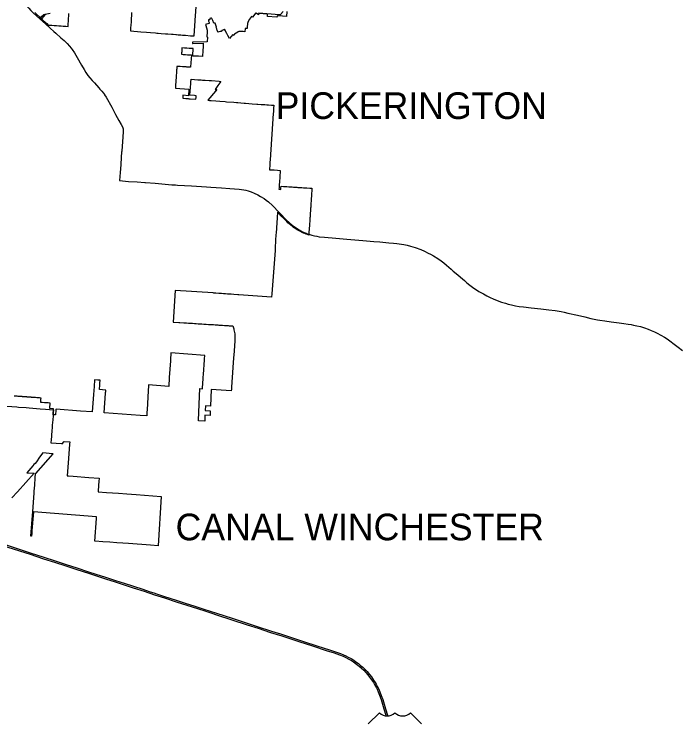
# Model space of a CAD drawing. Extents: x 1801177 to 2073177, y 551183 to 727183.
# Drawn here: x 1891384 to 1919316, y 663604 to 693418 of the extents above; entities that cross this region are included whole.
import ezdxf

# ---------------------------------------------------------------- set-up
doc = ezdxf.new("R2010")
doc.units = 0
for name, color, linetype in [('GM_X_Corporation', 7, 'Continuous'), ('GM_X_Corporation_Text', 7, 'Continuous'), ('GM_X_State_Route', 7, 'Continuous'), ('GM_X_US_Shield', 7, 'Continuous'), ('UT_P_Electric', 7, 'Continuous')]:
    doc.layers.add(name, color=color, linetype=linetype)

msp = doc.modelspace()

# ---------------------------------------------------------------- linework, layer by layer
at = {"layer": 'GM_X_Corporation'}
for points in [[(1901546, 693471), (1901398, 693294), (1901361, 693325), (1901361, 693325), (1901269, 693214), (1901224, 693105), (1901191, 693027), (1901179, 692875), (1901175, 692815), (1901136, 692818), (1901092, 692822), (1901081, 692677), (1901001, 692684), (1900921, 692690), (1900841, 692696), (1900824, 692697), (1900787, 692674), (1900780, 692669), (1900715, 692627), (1900643, 692582), (1900614, 692529), (1900600, 692538), (1900586, 692548), (1900574, 692558), (1900428, 692395), (1900362, 692521), (1900315, 692610), (1900269, 692699), (1900260, 692715), (1900220, 692793), (1900217, 692791), (1900202, 692781), (1900151, 692749), (1900115, 692726), (1900104, 692719), (1900096, 692714), (1900098, 692700), (1900098, 692686), (1900038, 692686), (1899944, 692665), (1899942, 692670), (1899918, 692741), (1899906, 692776), (1899896, 692805), (1899887, 692834), (1899877, 692862), (1899891, 692867), (1899827, 693044), (1899827, 693045), (1899778, 693044), (1899727, 693147), (1899670, 693262), (1899661, 693258), (1899644, 693250), (1899627, 693244), (1899622, 693241), (1899617, 693238), (1899612, 693234), (1899609, 693229), (1899606, 693224), (1899604, 693218), (1899604, 693212), (1899604, 693206), (1899606, 693190), (1899593, 693188), (1899576, 693186), (1899560, 693184), (1899546, 693183), (1899549, 693165), (1899550, 693154), (1899553, 693137), (1899557, 693120), (1899573, 693065), (1899584, 693030), (1899581, 693029), (1899566, 693024), (1899428, 692983), (1899440, 692942), (1899498, 692747), (1899495, 692702), (1899493, 692678), (1899475, 692460), (1899514, 692456), (1899497, 692257), (1898898, 692243), (1898880, 692243), (1898876, 692183), (1898894, 692183), (1899331, 692195), (1899321, 692045), (1899311, 691895), (1899293, 691645), (1899133, 691648), (1898886, 691654), (1898894, 691765), (1898903, 691890), (1898909, 691973), (1898879, 691975), (1898837, 691977), (1898737, 691983), (1898636, 691989), (1898536, 691995), (1898535, 691995), (1898435, 692001), (1898428, 691902), (1898426, 691866), (1898424, 691839), (1898421, 691790), (1898417, 691732), (1898492, 691728), (1898582, 691722), (1898672, 691717), (1898818, 691708), (1898830, 691707), (1898795, 691208), (1898793, 691189), (1898781, 691190), (1898634, 691198), (1898607, 691200), (1898544, 691204), (1898455, 691209), (1898365, 691214), (1898275, 691220), (1898223, 691223), (1898218, 691153), (1898215, 691119), (1898212, 691078), (1898207, 691003), (1898206, 690994), (1898193, 690803), (1898188, 690728), (1898183, 690662), (1898179, 690611), (1898176, 690569), (1898169, 690459), (1898163, 690384), (1898158, 690304), (1898729, 690271), (1898709, 689993), (1898475, 690012), (1898474, 690008), (1898466, 689889), (1898481, 689887), (1898593, 689878), (1898611, 689876), (1898694, 689869), (1898730, 689866), (1898735, 689866), (1898775, 689863), (1899020, 689844), (1899025, 689923), (1899030, 689993), (1898958, 689999), (1898770, 690013), (1898782, 690178), (1898794, 690343), (1898805, 690507), (1898806, 690516), (1898806, 690521), (1898809, 690564), (1898818, 690688), (1899106, 690666), (1899222, 690657), (1899249, 690655), (1899294, 690652), (1899318, 690651), (1899404, 690645), (1899417, 690644), (1899575, 690633), (1899634, 690629), (1899677, 690626), (1900000, 690602), (1900070, 690597), (1899946, 690421), (1899833, 690261), (1899904, 690256), (1899845, 690186), (1899525, 689803), (1899556, 689801), (1899562, 689800), (1899592, 689798), (1899597, 689798), (1899660, 689793), (1899863, 689776), (1900023, 689764), (1900249, 689746), (1900254, 689745), (1900304, 689741), (1900611, 689718), (1900729, 689709), (1900778, 689705), (1900906, 689695), (1901046, 689683), (1901065, 689682), (1901105, 689679), (1901379, 689657), (1901578, 689642), (1901608, 689640), (1901616, 689639), (1901622, 689639), (1901764, 689629), (1901816, 689625), (1901919, 689617), (1901922, 689617), (1901995, 689612), (1902071, 689606), (1902075, 689606), (1902199, 689597), (1902207, 689596), (1902293, 689590), (1902285, 689468), (1902275, 689310), (1902270, 689240), (1902139, 687299), (1902132, 687198), (1902122, 687046), (1902115, 686941), (1902112, 686886), (1902199, 686881), (1902309, 686873), (1902446, 686864), (1902564, 686856), (1902559, 686783), (1902550, 686636), (1902542, 686517), (1902536, 686434), (1902531, 686354), (1902525, 686258), (1902521, 686196), (1902515, 686117), (1902510, 686064), (1902592, 686059), (1902593, 686065), (1902593, 686071), (1902595, 686102), (1902601, 686190), (1902706, 686183), (1902772, 686179), (1902825, 686175), (1902849, 686174), (1902930, 686168), (1902962, 686166), (1902992, 686164), (1903071, 686159), (1903128, 686155), (1903191, 686151), (1903261, 686146), (1903311, 686143), (1903331, 686142), (1903401, 686137), (1903441, 686134), (1903470, 686132), (1903540, 686128), (1903561, 686126), (1903610, 686123), (1903680, 686118), (1903680, 686118), (1903806, 686110), (1903807, 686110), (1903898, 686104), (1903898, 686100), (1903893, 686026), (1903890, 685981), (1903885, 685904), (1903880, 685840), (1903879, 685826), (1903877, 685795), (1903875, 685756), (1903870, 685687), (1903868, 685654), (1903865, 685617), (1903863, 685581), (1903860, 685547), (1903857, 685497), (1903856, 685477), (1903851, 685407), (1903849, 685381), (1903846, 685337), (1903844, 685312), (1903841, 685267), (1903840, 685246), (1903839, 685235), (1903837, 685204), (1903824, 685011), (1903817, 684913), (1903817, 684908), (1903814, 684866), (1903814, 684863), (1903810, 684805), (1903808, 684786), (1903807, 684772), (1903793, 684556), (1903771, 684248), (1903768, 684197), (1903767, 684180), (1903764, 684141), (1903708, 684159), (1903652, 684180), (1903596, 684201), (1903541, 684225), (1903480, 684252), (1903420, 684282), (1903359, 684314), (1903299, 684348), (1903240, 684384), (1903183, 684422), (1903126, 684461), (1903065, 684507), (1903005, 684555), (1902947, 684604), (1902890, 684656), (1902836, 684710), (1902826, 684719), (1902798, 684748), (1902656, 684892), (1902637, 684911), (1902447, 685104), (1902445, 685080), (1902388, 684216), (1902385, 684163), (1902369, 683915), (1902365, 683849), (1902355, 683653), (1902352, 683582), (1902347, 683499), (1902346, 683483), (1902209, 681674), (1902199, 681533), (1900821, 681628), (1900776, 681631), (1900617, 681642), (1900502, 681650), (1900422, 681656), (1900342, 681662), (1900263, 681667), (1900183, 681673), (1900103, 681679), (1899990, 681687), (1899855, 681696), (1899779, 681702), (1899742, 681705), (1898151, 681815), (1898060, 680482), (1898307, 680467), (1898352, 680464), (1898508, 680454), (1898627, 680446), (1898710, 680441), (1898716, 680440), (1898776, 680436), (1898796, 680435), (1898876, 680430), (1898956, 680425), (1899036, 680420), (1899116, 680415), (1899195, 680409), (1899275, 680404), (1899355, 680399), (1899455, 680393), (1899545, 680387), (1899557, 680386), (1899635, 680381), (1899703, 680377), (1899729, 680375), (1899754, 680374), (1899824, 680369), (1899904, 680364), (1899949, 680361), (1899984, 680359), (1900064, 680354), (1900144, 680348), (1900223, 680343), (1900228, 680343), (1900303, 680338), (1900383, 680333), (1900412, 680331), (1900451, 680329), (1900558, 680322), (1900560, 680322), (1900569, 680321), (1900583, 680283), (1900596, 680244), (1900608, 680204), (1900621, 680152), (1900633, 680099), (1900643, 680046), (1900651, 679992), (1900656, 679939), (1900660, 679885), (1900661, 679831), (1900661, 679776), (1900658, 679722), (1900654, 679667), (1900643, 679512), (1900625, 679252), (1900606, 678987), (1900578, 678575), (1900520, 677744), (1900513, 677646), (1900509, 677594), (1900499, 677595), (1899662, 677654), (1899633, 676952), (1899418, 676967), (1899410, 676768), (1899625, 676752), (1899617, 676556), (1899402, 676571), (1899393, 676346), (1899392, 676321), (1899125, 676339), (1899127, 676365), (1899182, 677688), (1899297, 677680), (1899304, 677787), (1899305, 677804), (1899307, 677829), (1899309, 677854), (1899316, 677954), (1899319, 678001), (1899321, 678034), (1899325, 678091), (1899327, 678114), (1899332, 678193), (1899337, 678254), (1899338, 678273), (1899340, 678304), (1899344, 678353), (1899348, 678415), (1899353, 678483), (1899358, 678556), (1899362, 678612), (1899362, 678612), (1899368, 678700), (1899381, 678882), (1899382, 678907), (1899384, 678932), (1899394, 679078), (1897973, 679184), (1897954, 678897), (1897951, 678848), (1897904, 678150), (1897879, 677780), (1897028, 677848), (1897025, 677798), (1897013, 677593), (1896968, 676798), (1896962, 676701), (1896953, 676540), (1896673, 676561), (1896295, 676588), (1895170, 676671), (1895226, 677499), (1895228, 677529), (1895231, 677566), (1895235, 677622), (1895215, 677624), (1894966, 677643), (1894979, 677842), (1894984, 677917), (1894993, 678042), (1894899, 678049), (1894760, 678060), (1894760, 678059), (1894740, 677769), (1894718, 677442), (1894718, 677442), (1894706, 677260), (1894668, 676708), (1894164, 676746), (1893142, 676825), (1893141, 676808), (1893140, 676788), (1893123, 676580), (1893023, 676588), (1893028, 676658), (1893040, 676798), (1893040, 676806), (1893041, 676816), (1893042, 676833), (1892881, 676846), (1892883, 676868), (1892898, 677078), (1892811, 677085), (1892789, 677086), (1892750, 677089), (1892699, 677093), (1892664, 677096), (1892560, 677104), (1892499, 677109), (1892507, 677202), (1892508, 677218), (1892509, 677237), (1892513, 677288), (1892454, 677293), (1892404, 677297), (1892394, 677297), (1892334, 677302), (1892274, 677307), (1892249, 677309), (1892214, 677311), (1892155, 677316), (1892110, 677319), (1892095, 677321), (1892058, 677323), (1892035, 677325), (1891975, 677330), (1891915, 677334), (1891911, 677335), (1891855, 677339), (1891796, 677344), (1891736, 677348), (1891722, 677349), (1891711, 677350), (1891676, 677353), (1891616, 677358), (1891556, 677362), (1891512, 677366), (1891505, 677366), (1891497, 677367), (1891437, 677371), (1891377, 677376)], [(1892246, 693483), (1892526, 693225), (1892600, 693158), (1892679, 693087), (1892754, 693021), (1892817, 692963), (1892859, 692960), (1892868, 692960), (1892965, 692953), (1893063, 692946), (1893161, 692939), (1893259, 692932), (1893332, 692927), (1893356, 692925), (1893445, 692919), (1893454, 692918), (1893552, 692911), (1893646, 692904), (1893656, 693044), (1893660, 693104), (1893671, 693244), (1893678, 693343), (1893685, 693443)], [(1896321, 693489), (1896312, 693361), (1896310, 693337), (1896305, 693260), (1896300, 693188), (1896300, 693180), (1896294, 693090), (1896286, 692976), (1896276, 692837), (1896268, 692716), (1896708, 692680), (1896944, 692662), (1897112, 692648), (1897317, 692632), (1897373, 692627), (1897439, 692622), (1897564, 692612), (1897749, 692597), (1897791, 692594), (1897835, 692590), (1897999, 692577), (1898024, 692575), (1898059, 692572), (1898059, 692572), (1898179, 692563), (1898210, 692560), (1898271, 692555), (1898278, 692555), (1898340, 692550), (1898370, 692548), (1898378, 692547), (1898394, 692546), (1898452, 692541), (1898508, 692537), (1898582, 692531), (1898788, 692514), (1898874, 692507), (1898886, 692506), (1898916, 692504), (1898946, 692502), (1898991, 693145), (1898995, 693203), (1898995, 693205), (1898996, 693221), (1899002, 693299), (1899006, 693353), (1899032, 693729)], [(1902848, 693526), (1902833, 693326), (1902493, 693351), (1902457, 693354), (1902411, 693298), (1902026, 693326), (1902033, 693416), (1901648, 693443), (1901645, 693388), (1901558, 693460)], [(1901651, 693473), (1902541, 693410), (1902578, 693407), (1902685, 693537)], [(1892903, 693446), (1892683, 693400), (1892544, 693244), (1892483, 693299), (1892597, 693381), (1892625, 693401), (1892673, 693421)], [(1890647, 676984), (1891489, 676919), (1891560, 676913), (1891888, 676888), (1892020, 676877), (1892480, 676842), (1892703, 676824), (1893040, 676798), (1893028, 676658), (1893023, 676588), (1893019, 676539), (1893005, 676369), (1892987, 676150), (1892978, 676034), (1892970, 675931), (1892969, 675924), (1892936, 675511), (1892931, 675452), (1892927, 675411), (1893369, 675376), (1893407, 675373), (1893490, 675467), (1893718, 675449), (1893712, 675358), (1893668, 674752), (1893614, 674022), (1893664, 674019), (1893864, 674003), (1894524, 673953), (1894950, 673921), (1894942, 673790), (1894932, 673628), (1894915, 673365), (1894914, 673355), (1895259, 673328), (1895773, 673289), (1896113, 673263), (1896516, 673232), (1897565, 673149), (1897434, 671084), (1897115, 671106), (1896194, 671173), (1895943, 671192), (1895693, 671211), (1895399, 671233), (1895107, 671255), (1895103, 671255), (1894791, 671278), (1894778, 671279), (1894840, 672232), (1894844, 672285), (1894845, 672301), (1892197, 672517), (1892131, 671723), (1892123, 671617), (1892113, 671483), (1892082, 671485), (1892166, 672520), (1892223, 673300), (1892230, 673383), (1892239, 673507), (1892248, 673631), (1892270, 673937), (1892284, 674127), (1892292, 674127), (1893025, 674944), (1892988, 674948), (1892588, 674986), (1892453, 674803), (1892315, 674615), (1892263, 674545), (1892215, 674492), (1892165, 674436), (1892081, 674341), (1891914, 674155), (1892224, 674132), (1891520, 673351), (1891291, 673104)]]:
    msp.add_lwpolyline(points, dxfattribs=at)
at = {"layer": 'GM_X_State_Route'}
msp.add_line((1897304, 686317), (1897442, 686306), dxfattribs=at)
for points in [[(1891870, 693803), (1891996, 693670), (1892086, 693577), (1892184, 693481), (1892465, 693225)], [(1892465, 693225), (1892697, 693014), (1892891, 692837), (1893046, 692697)], [(1893046, 692697), (1893132, 692619), (1893344, 692430), (1893478, 692306), (1893604, 692189), (1893709, 692076), (1893777, 691996), (1893826, 691931), (1893915, 691796), (1894036, 691599), (1894218, 691275), (1894323, 691097), (1894398, 690968), (1894485, 690842), (1894565, 690743), (1894664, 690638), (1894757, 690533), (1894944, 690323), (1894990, 690272), (1895072, 690182), (1895136, 690102), (1895173, 690047)], [(1895173, 690047), (1895182, 690035), (1895246, 689931), (1895482, 689509), (1895648, 689205), (1895788, 688947), (1895881, 688778), (1895929, 688684), (1895946, 688638), (1895957, 688600), (1895964, 688555), (1895963, 688472), (1895947, 688260), (1895904, 687667), (1895900, 687620)], [(1895900, 687620), (1895885, 687406), (1895861, 687094), (1895838, 686768), (1895811, 686424)], [(1895811, 686424), (1896186, 686394), (1896551, 686369), (1896876, 686344)], [(1896876, 686344), (1896908, 686342), (1897304, 686317)], [(1897442, 686306), (1898013, 686253), (1898166, 686244)], [(1898166, 686244), (1898253, 686239), (1898833, 686201)], [(1898833, 686201), (1899470, 686160), (1899655, 686147), (1900103, 686119), (1900447, 686098), (1900844, 686068), (1900935, 686057), (1901036, 686039), (1901119, 686021), (1901221, 685995), (1901337, 685956), (1901469, 685904), (1901629, 685828), (1901741, 685763), (1901887, 685674), (1901979, 685606), (1902070, 685532), (1902240, 685374), (1902524, 685085), (1902861, 684743), (1902903, 684703), (1902960, 684650), (1903070, 684555), (1903144, 684499), (1903230, 684436), (1903360, 684360), (1903504, 684281), (1903660, 684212), (1903670, 684208)], [(1903670, 684208), (1903765, 684170), (1903886, 684133), (1904001, 684104), (1904097, 684086), (1904206, 684071), (1904421, 684047), (1904901, 684005), (1905367, 683964), (1906039, 683908), (1906495, 683867)], [(1906495, 683867), (1906756, 683848), (1907132, 683813), (1907327, 683796), (1907470, 683786), (1907569, 683771), (1907754, 683739), (1907894, 683709), (1908045, 683669), (1908234, 683613), (1908468, 683526), (1908627, 683461), (1908786, 683382), (1908881, 683332), (1909000, 683264), (1909185, 683150), (1909323, 683051), (1909434, 682967), (1909546, 682880), (1909650, 682793), (1909746, 682709), (1909839, 682625), (1910022, 682469), (1910146, 682364), (1910306, 682229), (1910409, 682137), (1910536, 682035), (1910706, 681913), (1910818, 681836), (1910918, 681772), (1911103, 681663), (1911251, 681583), (1911386, 681519), (1911513, 681459), (1911676, 681394)], [(1911676, 681394), (1911869, 681323), (1912026, 681272), (1912146, 681238), (1912291, 681202), (1912446, 681169), (1912610, 681138), (1912792, 681117), (1913108, 681081), (1913522, 681034), (1913859, 680997), (1914120, 680965), (1914197, 680955), (1914378, 680924), (1914501, 680897), (1914651, 680861), (1915056, 680769), (1915360, 680698), (1915614, 680639), (1915762, 680607), (1915905, 680579), (1915992, 680567), (1916203, 680534), (1916470, 680497), (1916805, 680450), (1917005, 680425), (1917187, 680398), (1917311, 680379), (1917412, 680359), (1917555, 680329), (1917700, 680292), (1917871, 680240), (1918025, 680186), (1918149, 680135), (1918293, 680075), (1918412, 680014), (1918566, 679934), (1918713, 679844), (1918824, 679774), (1918943, 679691), (1919124, 679554), (1919291, 679425), (1919469, 679285)]]:
    msp.add_lwpolyline(points, dxfattribs=at)
at = {"layer": 'GM_X_US_Shield'}
for p, q in [((1906732, 664071), (1906265, 663604)), ((1908506, 663604), (1908040, 664071))]:
    msp.add_line(p, q, dxfattribs=at)
for centre in [(1907059, 664405), (1907713, 664405)]:
    msp.add_arc(centre, 467, 225.573, 314.427, dxfattribs=at)
at = {"layer": 'UT_P_Electric'}
for points in [[(1890787, 671202), (1890898, 671166), (1891124, 671092), (1892060, 670789), (1892626, 670605), (1893109, 670449), (1893564, 670300), (1894020, 670153), (1894508, 669995), (1894810, 669896), (1895223, 669762), (1895637, 669628), (1896011, 669507), (1896397, 669381), (1896789, 669256), (1897055, 669169), (1897291, 669093), (1897321, 669083)], [(1890793, 671134), (1891118, 671029), (1892055, 670726), (1892620, 670542), (1893082, 670391), (1893559, 670237), (1894014, 670090), (1894502, 669931), (1894805, 669833), (1895217, 669699), (1895631, 669565), (1896006, 669444), (1896391, 669318), (1896840, 669173), (1897286, 669029)], [(1897286, 669029), (1897701, 668894), (1898196, 668734), (1898644, 668588), (1899086, 668444), (1899433, 668330), (1899695, 668246), (1899882, 668180), (1901175, 667766), (1901637, 667616), (1902160, 667446), (1902628, 667295), (1903342, 667062), (1903920, 666876), (1904493, 666690), (1904829, 666580), (1905050, 666506), (1905214, 666440), (1905317, 666391), (1905422, 666338), (1905555, 666261), (1905649, 666202), (1905775, 666112), (1905876, 666032), (1905980, 665944), (1906073, 665854), (1906157, 665766), (1906245, 665667), (1906322, 665570), (1906405, 665457), (1906478, 665344), (1906528, 665257), (1906574, 665181), (1906609, 665119), (1906635, 665059)], [(1897321, 669083), (1897485, 669029), (1897702, 668959), (1898189, 668801), (1898567, 668679), (1898979, 668546), (1899358, 668422), (1899624, 668335), (1899888, 668249), (1900539, 668039), (1901045, 667873), (1901592, 667696), (1902192, 667503), (1902574, 667380), (1902999, 667241), (1903494, 667082), (1904147, 666869), (1904632, 666710), (1904892, 666627), (1905091, 666559), (1905228, 666504), (1905321, 666460), (1905423, 666408), (1905541, 666344), (1905653, 666273), (1905749, 666208), (1905853, 666132), (1905944, 666057), (1906031, 665979), (1906121, 665895), (1906217, 665797), (1906314, 665682), (1906398, 665574), (1906489, 665444), (1906551, 665344), (1906597, 665267), (1906641, 665186), (1906706, 665054)], [(1906635, 665059), (1906678, 664954), (1906739, 664805), (1906800, 664626), (1906862, 664429), (1906921, 664234), (1907004, 663973), (1907014, 663940)], [(1906706, 665054), (1906749, 664949), (1906810, 664800), (1906871, 664621), (1906933, 664424), (1906992, 664229), (1907075, 663968), (1907084, 663938)]]:
    msp.add_lwpolyline(points, dxfattribs=at)

# ---------------------------------------------------------------- texts
at = {"layer": 'GM_X_Corporation_Text'}
for s, p in [('PICKERINGTON', (1902372, 689015)), ('CANAL WINCHESTER', (1898167, 671314))]:
    msp.add_text(s, height=1120, rotation=0, dxfattribs=at).set_placement(p)

doc.saveas('drawing.dxf')
